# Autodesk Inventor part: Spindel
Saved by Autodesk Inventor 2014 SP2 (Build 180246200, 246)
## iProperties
Created: 2015-06
Part Number: Spindel
Material: Generisch
Document SubType Name: Modeling
Designer: e_krauts
Density: 1 g/cm^3
Appearance: Vorgabe
Mass: 562.173 g
Surface Area: 590.667 cm^2
Volume: 562.173 cm^3
Sending System: SolidWorks 2011
Last Author: e_boekem
Author: e_krauts
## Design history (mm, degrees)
node "Spindel.ipt1"
node "Aufsatz-Linear austragen2"
node "Basis1"
